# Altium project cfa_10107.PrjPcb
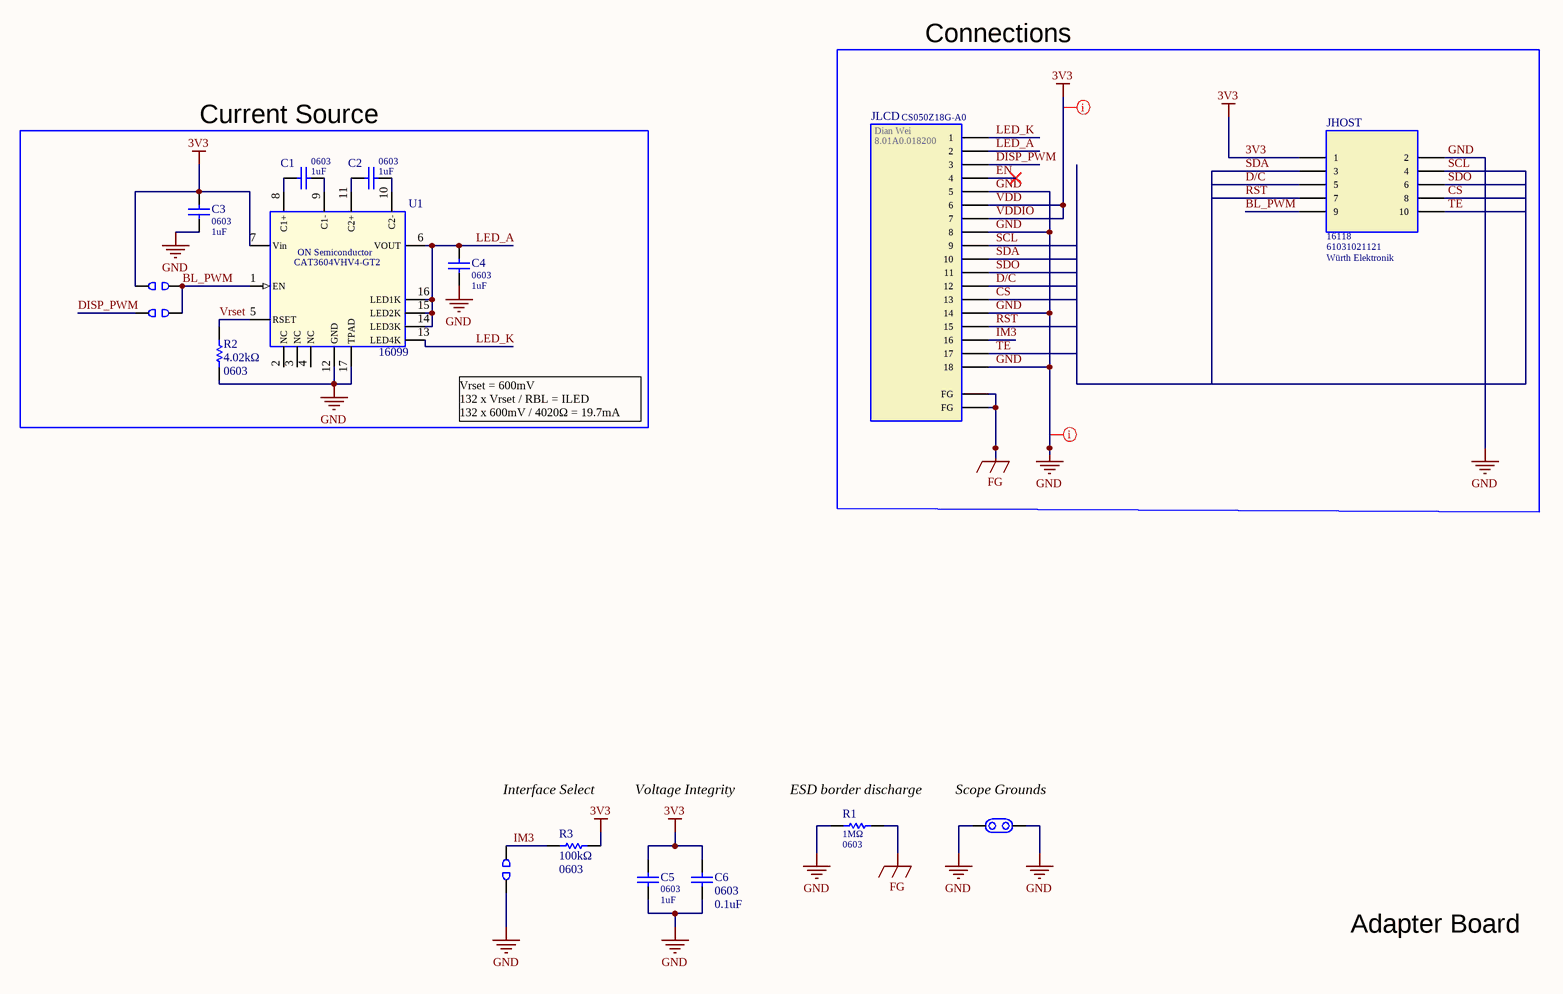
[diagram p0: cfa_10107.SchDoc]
PCBNumber: CFA10107; PCBRev: 0v1; ProjectDesc: CFA-10107: CFAF240240A1-013T Adapter Board
1 sheet, 16 parts. Net scope: global (net labels, ports and power ports of the same name join across sheets).
Board file: cfa_10107.PcbDoc

## Sheet cfa_10107.SchDoc
size OrCAD B; DocumentNumber: 1; SheetNumber: 1; SheetTotal: 1

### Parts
*3  Scope contact .1"  [Scope_Contact]  (value not drawn)
C1  value 1uF  PACKAGE: 0603  [00289_CAM]  (hidden comment: CAP CER 1UF 25V X5R 0603)
C2  value 1uF  PACKAGE: 0603  [00289_CAM]  (hidden comment: CAP CER 1UF 25V X5R 0603)
C3  value 1uF  PACKAGE: 0603  [00289_CAM]  (hidden comment: CAP CER 1UF 25V X5R 0603)
C4  value 1uF  PACKAGE: 0603  [00289_CAM]  (hidden comment: CAP CER 1UF 25V X5R 0603)
C5  value 1uF  PACKAGE: 0603  [00289_CAM]  (hidden comment: CAP CER 1UF 25V X5R 0603)
C6  value 0.1uF  PACKAGE: 0603  [00133_CAM]  (hidden comment: CAP CER 0.1UF 25V X7R 0603)
IM3  Jumper_Open  [Jumper_7mil_gap_open]  (value not drawn)
JHOST  CFAPN: 16118  MFGPN: 61031021121  MFG: Würth Elektronik  [16118_CAM]  (hidden comment: CONN HEADER SMD 10POS 2.54MM)
JLCD  MFGPN: 8.01A0.018200  MFG: Dian Wei  [CS050Z18G-A0_CAM]  (hidden comment: CONN FPC BOTTOM 18POS 0.30MM R/A)
PWM->3.3V  Jumper_Open  [Jumper_7mil_gap_open]  (value not drawn)
PWM->DISP_PWM  Jumper_Open  [Jumper_7mil_gap_open]  (value not drawn)
R1  value 1MΩ  PACKAGE: 0603  [16110_CAM]  (hidden comment: RES SMD 1M OHM 1% 1/10W 0603)
R2  value 4.02kΩ  PACKAGE: 0603  [16110_CAM]  (hidden comment: RES SMD 4.02K OHM 1% 1/10W 0603)
R3  value 100kΩ  PACKAGE: 0603  [16110_CAM]  (hidden comment: RES SMD 100K OHM 1% 1/10W 0603)
U1  CFAPN: 16099  MFG: ON Semiconductor  MFGPN: CAT3604VHV4-GT2  [16099_CAM]  (hidden comment: IC LED DRIVER RGLTR DIM SOT23-6)

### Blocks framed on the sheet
Connections: JHOST JLCD
Current Source: C1-C4 PWM->3.3V PWM->DISP_PWM R2 U1

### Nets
3V3: C3.1 C5.1 C6.2 JHOST.1 JLCD.6 JLCD.7 PWM->3.3V.1 R3.2 U1.7(Vin)  [also labelled VDD, VDDIO]
FG: JLCD.FG1(FG) JLCD.FG2(FG) R1.2
GND: *3.1(OSC5) C3.2 C4.1 C5.2 C6.1 IM3.1 JHOST.2 JLCD.5 JLCD.8 JLCD.14 JLCD.18 R1.1 R2.1 U1.12(GND) U1.17(TPAD)
BL_PWM: JHOST.9 PWM->3.3V.2 PWM->DISP_PWM.2 U1.1(EN)
CS: JHOST.8 JLCD.13
D/C: JHOST.5 JLCD.12
DISP_PWM: JLCD.3 PWM->DISP_PWM.1
EN: JLCD.4
IM3: IM3.2 JLCD.16 R3.1
LED_A: C4.2 JLCD.2 U1.6(VOUT) U1.14(LED3K) U1.15(LED2K) U1.16(LED1K)
LED_K: JLCD.1 U1.13(LED4K)
RST: JHOST.7 JLCD.15
SCL: JHOST.4 JLCD.9
SDA: JHOST.3 JLCD.10
SDO: JHOST.6 JLCD.11
TE: JHOST.10 JLCD.17
Vrset: R2.2 U1.5(RSET)
NetC1_1: C1.1 U1.9(C1-)
NetC1_2: C1.2 U1.8(C1+)
NetC2_1: C2.1 U1.10(C2-)
NetC2_2: C2.2 U1.11(C2+)

Not connected (* = marked no-connect by the designer): U1 2(NC) 3(NC) 4(NC)

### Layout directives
net class PowerNets: 3V3, GND

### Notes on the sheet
- Vrset = 600mV
  132 x Vrset / RBL = ILED
  132 x 600mV / 4020Ω = 19.7mA
- Interface Select
- Voltage Integrity
- (near R1) ESD border discharge
- (near *3) Scope Grounds
- Adapter Board

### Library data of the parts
*3 = Scope_Contact: Dual pin .1" spacing contact for scoping different lines. Through hole.
C1-C5 = 00289_SCH: 1µF ±10% 25V Ceramic Capacitor X5R 0603 (1608 Metric); SUBSTITUTE: OK; MFG: Murata Electronics; LOAD: ALL; MFGPN: GRM188R61E105KA12D; CFAPN: 00289
C6 = 00133_SCH: 0.1µF ±10% 25V Ceramic Capacitor X7R 0603 (1608 Metric); LOAD: ALL; MFG: TDK Corporation; MFGPN: C1608X7R1E104K080AA; SUBSTITUTE: OK; CFAPN: 00133
IM3 PWM->3.3V PWM->DISP_PWM = Jumper_Open: Open jumper
JHOST = 16118_SCH: Connector Header Surface Mount 10 position 0.100" (2.54mm); LOAD: ALL; SUBSTITUTE: OK
JLCD = CS050Z18G-A0: 18 Position FPC Connector Contacts, Top/Bottom, 0.50mm, Surface Mount, Right Angle; LOAD: ALL; SUBSTITUTE: EXACT
R1 = 00191_SCH: 1 MOhms ±1% 0.1W, 1/10W Chip Resistor 0603 (1608 Metric) Automotive AEC-Q200 Thick Film; MFGPN: ERJ-3EKF1004V; MFG: Panasonic Electronic Components; LOAD: ALL; CFAPN: 00191; SUBSTITUTE: OK
R2 = 03061_SCH: 4.02 kOhms ±1% 0.1W, 1/10W Chip Resistor 0603 (1608 Metric) Automotive AEC-Q200 Thick Film; MFGPN: ERJ-3EKF4021V; MFG: Panasonic Electronic Components; LOAD: ALL; CFAPN: 03061; SUBSTITUTE: OK
R3 = 00580_SCH: 100 kOhms ±1% 0.1W, 1/10W Chip Resistor 0603 (1608 Metric) Automotive AEC-Q200 Thick Film; MFGPN: ERJ-3EKF1003V; SUBSTITUTE: OK; MFG: Panasonic Electronic Components; LOAD: ALL; CFAPN: 00580
U1 = 16099_SCH: LED Driver IC 1 Output DC DC Regulator Step-Up (Boost) PWM Dimming 550mA (Switch) SOT-23-6; SUBSTITUTE: EXACT; LOAD: ALL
